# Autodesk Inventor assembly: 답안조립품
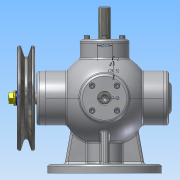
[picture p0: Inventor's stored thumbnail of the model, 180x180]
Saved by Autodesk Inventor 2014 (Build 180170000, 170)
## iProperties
Created: 2016-01
Part Number: 답안조립품
Document SubType Name: Assembly
Designer: Administrator
Mass: 3734.97 g
Surface Area: 2410.99 cm^2
Volume: 903.657 cm^3
Density: 4.13317 g/cm^3
Author: Administrator
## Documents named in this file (17)
- C:\Users\Administrator\Desktop\360108V1008\답안조립품.iam
- C:\Users\Administrator\Desktop\360108V1008\본체.ipt
- C:\Users\Administrator\Desktop\360108V1008\뒤커버.ipt
- C:\Users\Administrator\Desktop\360108V1008\베어링- 6202.ipt
- C:\Users\Administrator\Desktop\360108V1008\볼트 M4x0.7.ipt
- C:\Users\Administrator\Desktop\360108V1008\축.ipt
- C:\Users\Administrator\Desktop\360108V1008\키-4x4.ipt
- C:\Users\Administrator\Desktop\360108V1008\앞커버.ipt
- C:\Users\Administrator\Desktop\360108V1008\오일실.ipt
- C:\Users\Administrator\Desktop\360108V1008\V-벨트풀리.ipt
- C:\Users\Administrator\Desktop\360108V1008\너트-M8x1.ipt
- C:\Users\Administrator\Desktop\360108V1008\와셔 8x17.ipt
- C:\Users\Administrator\Desktop\360108V1008\슬라이드 커버.ipt
- C:\Users\Administrator\Desktop\360108V1008\슬라이드.ipt
- C:\Users\Administrator\Desktop\360108V1008\본체커버.ipt
- C:\Users\Administrator\Desktop\360108V1008\스프링1.ipt
- C:\Users\Administrator\Desktop\360108V1008\스프링2.ipt
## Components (18 placed, 2 different names)
1. V-벨트풀리:1 — 플러쉬:1, 각도:2
2. M4x0.7x12:17
3. M4x0.7x12:1
4. M4x0.7x12:2
5. M4x0.7x12:3
6. M4x0.7x12:4
7. M4x0.7x12:5
8. M4x0.7x12:6
9. M4x0.7x12:7
10. M4x0.7x12:8
11. M4x0.7x12:9
12. M4x0.7x12:11
13. M4x0.7x12:12
14. M4x0.7x12:13
15. M4x0.7x12:10
16. M4x0.7x12:14
17. M4x0.7x12:15
18. M4x0.7x12:16
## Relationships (2: Flush 1, Angle 1)
- 플러쉬:1 [Flush]: V-벨트풀리:1
- 각도:2 [Angle]: V-벨트풀리:1
